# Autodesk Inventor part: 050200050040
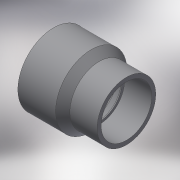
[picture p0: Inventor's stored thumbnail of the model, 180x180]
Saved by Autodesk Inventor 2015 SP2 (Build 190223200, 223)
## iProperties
Created: 2017-10
Part Number: 050200050040
Material: Generic
Description: PLASSON REDUCING SOCKET M.F.50(40)40 CEMENTED
Document SubType Name: Modeling
Designer: KIM
Density: 1 g/cm^3
Appearance: Default
Author: KIM
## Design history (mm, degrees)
derived "050200.ipt"
feature "Solid1::050200.ipt"
tag "TaggingFeature1"
body "Solid1"
other parameters: "d0" = 69, "d1" = 31, "d2" = 26, "d3" = 26, "d5" = 49, "d8" = 36, "d9" = 45 deg, "d12" = 0.4, "L_" = 31, "l_" = 26, "l_1" = 26, "E_" = 49, "H_" = 69, "d11" = 0.41643
